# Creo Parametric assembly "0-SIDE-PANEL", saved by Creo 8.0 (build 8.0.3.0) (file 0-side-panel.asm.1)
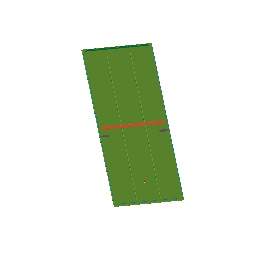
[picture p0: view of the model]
Units: millimeter Newton Second (mmNs); MM, TONNE, SECS

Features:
  1. datum plane "ADTM1"
  2. datum plane "ADTM2"
  3. datum plane "ADTM3"
  4. coordinate system
  5. component "1_SIDE_PANEL"
  6. component "1_SIDE_PANEL_RIB"
  7. component "3_GROUNDING_M8X20"
  8. component "4_GROUNDING_MARK"
  9. component "3_SIDE_PANEL_SPONGE1"
  10. component "1_SIDE_PANEL_USEAM"
  11. component "4_LOCK"
  12. component "4_LOCK"

Other named items: ACS0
